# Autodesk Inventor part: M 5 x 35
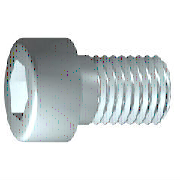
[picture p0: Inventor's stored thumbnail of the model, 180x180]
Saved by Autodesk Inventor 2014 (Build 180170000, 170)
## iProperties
IsCustomPart: 0
Company: 한국ATC센터
Created: 2014-12
Part Number: M 5 x 35
Material: 강, 연강
Description: 6각머리 태핑 나사
Document SubType Name: Modeling
Standard: KS B 1003
Designer: KYOUNG IL JANG
Standards Organization: KS
Language: ko-KR
Size Designation: M 5 x 35
Categories: <MemberInstance><Categories><Category DisplayName="조임쇠" InternalName="e4da775c-781d-43d5-af7c-5136215cf5a6" Mnemonic="FSTN"><Category DisplayName="볼트" InternalN
Density: 7.86 g/cm^3
Mass: 7.27786 g
Surface Area: 8.23857 cm^2
Volume: 0.925936 cm^3
Appearance: 광택 - 검은색
Author: KYOUNG IL JANG
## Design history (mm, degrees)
sketch "스케치1"
  geometry: L1 (-1.167, 0)-(35, 0); L2 (35, 0)-(35, 2.5); L3 (35, 2.5)-(13, 2.5); L4 (13, 2.5)-(12.509, 2.5); L5 (12.509, 2.5)-(0, 2.5); L6 (0, 2.5)-(0, 4.25); L7 (0, 4.25)-(-5, 4.25); L8 (-5, 4.25)-(-5, 2.309); L9 (-5, 2.309)-(-2.5, 2.309); L10 (-2.5, 2.309)-(-1.167, 0); L11 (-13, 0)-(43, 0) reference; L12 (0, -0.85)-(0, 5.1) reference; L13 (13, 2.5)-(0, 2.5)
  constraints: 22 end point, 6 parallel, 2 collinear, 2 perpendicular, 1 horizontal, 1 point on line
  dimensions: "d1" = 22 distance from line of L3.end L2 (= GEL); "d2" = 0.49086 distance of L4.end L3.end (computed from GAL); "d3" = 5 distance between parallel lines of L8 L6 (= KOH); "d4" = 2.5 distance of L8.end L9.end (= INTI); "d5" = 60 deg angle of L10 L1; "d6" = 5 diameter of L3 L1 (= GD); "d7" = 5 diameter of L5 L1 (= BDM); "d8" = 4.6188 diameter of L9 L1 (= 1.1547 x SW); "d9" = 8.5 diameter of L7 L1 (= KOD); "d26" = 35 distance between parallel lines of L12 L2 (= NLG)
revolve "본체" sketch "스케치1" stored, may be unused: angle "d10" = 90 deg
sketch "스케치2"
  geometry: L1 (0, -5.95)-(0, 5.95) reference; L2 (-5.95, 0)-(5.95, 0) reference; L3 (2.309, 0)-(1.155, -2); L4 (1.155, -2)-(-1.155, -2); L5 (-1.155, -2)-(-2.309, 0); L6 (-2.309, 0)-(-1.155, 2); L7 (-1.155, 2)-(1.155, 2); L8 (1.155, 2)-(2.309, 0); 2 further points
  constraints: 12 end point, 1 coincident, 1 horizontal alignment, 1 point on line, 12 other
extrude "슬롯" join sketch "스케치2" stored distance "d11" = 10; taper "d12" = 0 deg
workplane "Work Plane1"
fillet "Fillet2" dims "d30" = 0.1 (= R)
body "Solid1"
fillet "모깎기1" dims "d17" = 0.5 (= RR)
feature "스레드" dims "d13" = 22 (= GEL), "d14" = 0
chamfer "모따기1" distance "d15" = 0.49076 (= -0.5 x SPD + 0.5 x GD); stored, may be unused: second distance "d16" = 0.49076 (= GUL), angle "d27" = 45 deg
other parameters: "GD" = 5 (= NND) [user parameter; used in 2 equation terms], "NLG" = 35 [user parameter; used in 1 equation term], "GEL" = 22 [user parameter; used in 2 equation terms], "KOD" = 8.5 [user parameter; used in 1 equation term], "KOH" = 5 [user parameter; used in 1 equation term], "INTI" = 2.5 [user parameter; used in 1 equation term], "GAL" = 0.49076 (= 0.61345 x PTC) [user parameter; used in 1 equation term], "GUL" = 0.49076 (= 0.61345 x PTC) [user parameter; used in 1 equation term], "BDM" = 5 (= NND) [user parameter; used in 1 equation term], "SW" = 4 [user parameter; used in 2 equation terms], "RR" = 0.5 [user parameter; used in 1 equation term], "SPD" = 4.01848 (= NND - 1.2269 x PTC) [user parameter; used in 1 equation term], "d19" = 0, "d28" = 0, "d29" = 0, "R" = 0.1 [user parameter; used in 1 equation term], "PHH" = 0.2 [user parameter], "GD1" = 4.01848 (= THREADDIA - 1.2269 x PTC) [user parameter], "THREADDIA" = 5 [user parameter; used in 1 equation term], "FAWI" = 45 deg [user parameter], "TPU" = 12.5 (computed from PTC) [user parameter], "PTC" = 0.8 [user parameter; used in 5 equation terms], "NND" = 5 [user parameter; used in 3 equation terms], "TOA" = 30 deg [user parameter], "E0" = 4.62 (= 1.155 x SW) [user parameter]
